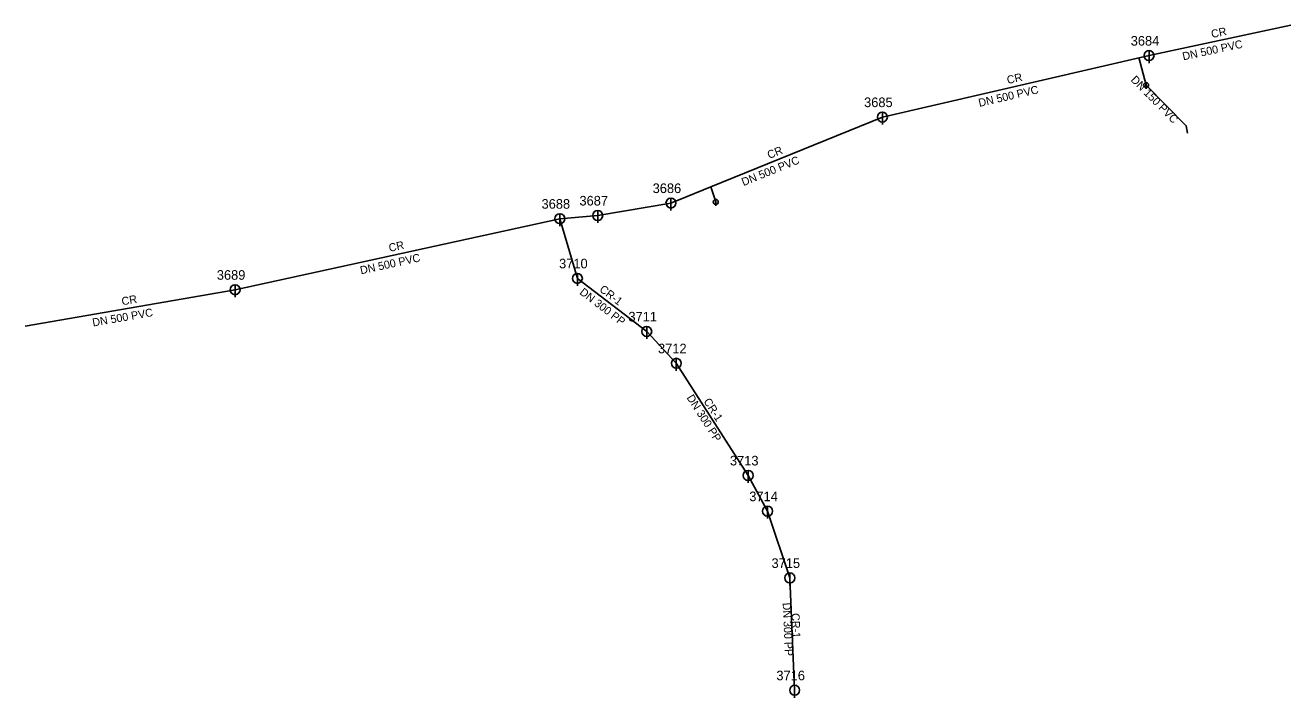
# Model space of a CAD drawing. Extents: x -472775 to -472521, y -1121026 to -1120892.
import ezdxf

# ---------------------------------------------------------------- set-up
doc = ezdxf.new("R2010")
doc.units = 0
for name, color, linetype in [('_pripojka_kanal_splaskova_prevzato_z_dokumentace_', 7, 'Continuous'), ('_pripojka_kanal_splaskova_priblizne_', 7, 'Continuous'), ('_stoka_splaskova_provozovana_prevzato_z_dokumentace_', 7, 'Continuous'), ('Default', 7, 'Continuous'), ('MoLevel 119', 7, 'Continuous'), ('MoLevel 120', 7, 'Continuous'), ('MoLevel 57', 7, 'Continuous'), ('MoLevel 60', 7, 'Continuous'), ('MoLevel 84', 7, 'Continuous'), ('MoLevel 85', 7, 'Continuous')]:
    doc.layers.add(name, color=color, linetype=linetype)

# ---------------------------------------------------------------- blocks, each defined once
blk = doc.blocks.new('_sachta_kanal_prip_')
at = {"layer": 'Default'}
blk.add_line((0, 0.05), (0, -0.075), dxfattribs=at)
blk.add_circle((0, 0), 0.05, dxfattribs=at)
blk = doc.blocks.new('_sachta_kanal_prevzato_z_dokumentace_')
at = {"layer": 'Default'}
blk.add_line((0, 0.05), (0, -0.075), dxfattribs=at)
blk.add_circle((0, 0), 0.05, dxfattribs=at)

msp = doc.modelspace()

# ---------------------------------------------------------------- linework, layer by layer
at = {"layer": '_pripojka_kanal_splaskova_prevzato_z_dokumentace_'}
msp.add_line((-472636.1, -1120926.95), (-472637.11, -1120923.92), dxfattribs=at)
at = {"layer": '_pripojka_kanal_splaskova_priblizne_'}
msp.add_line((-472549.81, -1120903.52), (-472551.27, -1120897.96), dxfattribs=at)
msp.add_lwpolyline([(-472541.52, -1120913.18), (-472541.76, -1120911.68), (-472549.81, -1120903.52)], dxfattribs=at)
at = {"layer": '_stoka_splaskova_provozovana_prevzato_z_dokumentace_'}
for p, q in [((-472549.23, -1120897.59), (-472520.82, -1120891.52)), ((-472602.7, -1120909.93), (-472549.23, -1120897.59)), ((-472659.78, -1120929.67), (-472645.1, -1120927.17)), ((-472732.5, -1120944.56), (-472667.38, -1120930.31)), ((-472667.38, -1120930.31), (-472659.78, -1120929.67)), ((-472663.86, -1120942.28), (-472667.38, -1120930.31)), ((-472649.96, -1120952.93), (-472663.86, -1120942.28)), ((-472774.57, -1120951.89), (-472732.5, -1120944.56)), ((-472644.02, -1120959.32), (-472649.96, -1120952.93)), ((-472629.61, -1120981.81), (-472644.02, -1120959.32)), ((-472625.72, -1120988.98), (-472629.61, -1120981.81)), ((-472621.26, -1121002.37), (-472625.72, -1120988.98)), ((-472620.29, -1121024.9), (-472621.26, -1121002.37))]:
    msp.add_line(p, q, dxfattribs=at)
msp.add_lwpolyline([(-472645.1, -1120927.17), (-472637.11, -1120923.92), (-472602.7, -1120909.93)], dxfattribs=at)

# ---------------------------------------------------------------- block references
at = {"layer": 'MoLevel 119', "xscale": 20, "yscale": 20}
for p in [(-472549.23, -1120897.59), (-472602.7, -1120909.93), (-472645.1, -1120927.17), (-472667.38, -1120930.31), (-472659.78, -1120929.67), (-472663.86, -1120942.28), (-472732.5, -1120944.56), (-472649.96, -1120952.93), (-472644.02, -1120959.32), (-472629.61, -1120981.81), (-472625.72, -1120988.98), (-472621.26, -1121002.37), (-472620.29, -1121024.9)]:
    msp.add_blockref('_sachta_kanal_prevzato_z_dokumentace_', p, dxfattribs=at)
at = {"layer": 'MoLevel 57', "xscale": 10, "yscale": 10}
for p in [(-472549.81, -1120903.52), (-472636.1, -1120926.95)]:
    msp.add_blockref('_sachta_kanal_prip_', p, dxfattribs=at)

# ---------------------------------------------------------------- texts
at = {"layer": 'MoLevel 120'}
for s, p in [('3684', (-472552.9, -1120895.59)), ('3685', (-472606.37, -1120907.93)), ('3686', (-472648.77, -1120925.17)), ('3688', (-472671.05, -1120928.31)), ('3687', (-472663.45, -1120927.67)), ('3689', (-472736.17, -1120942.56)), ('3710', (-472667.53, -1120940.28)), ('3711', (-472653.63, -1120950.93)), ('3712', (-472647.69, -1120957.32)), ('3713', (-472633.27, -1120979.81)), ('3714', (-472629.39, -1120986.98)), ('3715', (-472624.93, -1121000.37)), ('3716', (-472623.96, -1121022.9))]:
    msp.add_text(s, height=1.926, dxfattribs=at).set_placement(p)
at = {"layer": 'MoLevel 60'}
msp.add_text('DN 150 PVC', height=1.605, rotation=314.6169, dxfattribs=at).set_placement((-472553, -1120902.58))
at = {"layer": 'MoLevel 84'}
for s, rotation, p in [('DN 500 PVC', 12.0603, (-472542.35, -1120898.56)), ('DN 500 PVC', 12.9954, (-472583.24, -1120907.89)), ('DN 500 PVC', 22.1268, (-472630.55, -1120923.79)), ('DN 500 PVC', 12.3433, (-472707.25, -1120941.48)), ('DN 300 PP', 322.5549, (-472663.56, -1120945.33)), ('DN 500 PVC', 9.8836, (-472760.98, -1120951.95)), ('DN 300 PP', 302.6461, (-472642.02, -1120966.22)), ('DN 300 PP', 272.4707, (-472622.69, -1121007.36))]:
    msp.add_text(s, height=1.605, rotation=rotation, dxfattribs=at).set_placement(p)
at = {"layer": 'MoLevel 85'}
for s, rotation, p in [('CR', 12.0603, (-472536.59, -1120894.09)), ('CR', 12.9954, (-472577.53, -1120903.32)), ('CR', 22.1268, (-472625.39, -1120918.35)), ('CR', 12.3433, (-472701.51, -1120936.98)), ('CR', 9.8836, (-472755.12, -1120947.7)), ('CR-1', 322.5549, (-472659.58, -1120944.76)), ('CR-1', 302.6461, (-472638.63, -1120966.94)), ('CR-1', 272.4707, (-472620.92, -1121009.47))]:
    msp.add_text(s, height=1.605, rotation=rotation, dxfattribs=at).set_placement(p)

doc.saveas('drawing.dxf')
